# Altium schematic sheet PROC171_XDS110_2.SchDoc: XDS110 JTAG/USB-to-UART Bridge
size 431 x 279 mm; Date: Not shown in title block; ApprovedBy: Not shown in title block; CheckedBy: Not shown in title block; Author: Not shown in title block; CompanyName: Not shown in title block; Engineer: Not shown in title block; Organization: Not shown in title block; Address1: Not shown in title block; Address2: Not shown in title block; Address3: Not shown in title block; Address4: Not shown in title block; DocumentNumber: 26; Revision: Use project parameter SCH_Rev; SheetNumber: 26; SheetTotal: 27; PageSetup: Record=PageOptions¦CenterHorizontal=True¦CenterVertical=True¦PrintScale=1.00¦XCorrection=1.00¦YCorrection=1.00¦PrintKind=0¦BorderSize=5000000¦LeftOffset=0¦BottomOffset=0¦Orientation=2¦PaperLength=1000¦PaperWidth=1000¦Scale=100¦PaperSource=15¦PrintQuality=600¦MediaType=1¦DitherType=10¦PaperKind=Letter¦PrintScaleMode=1
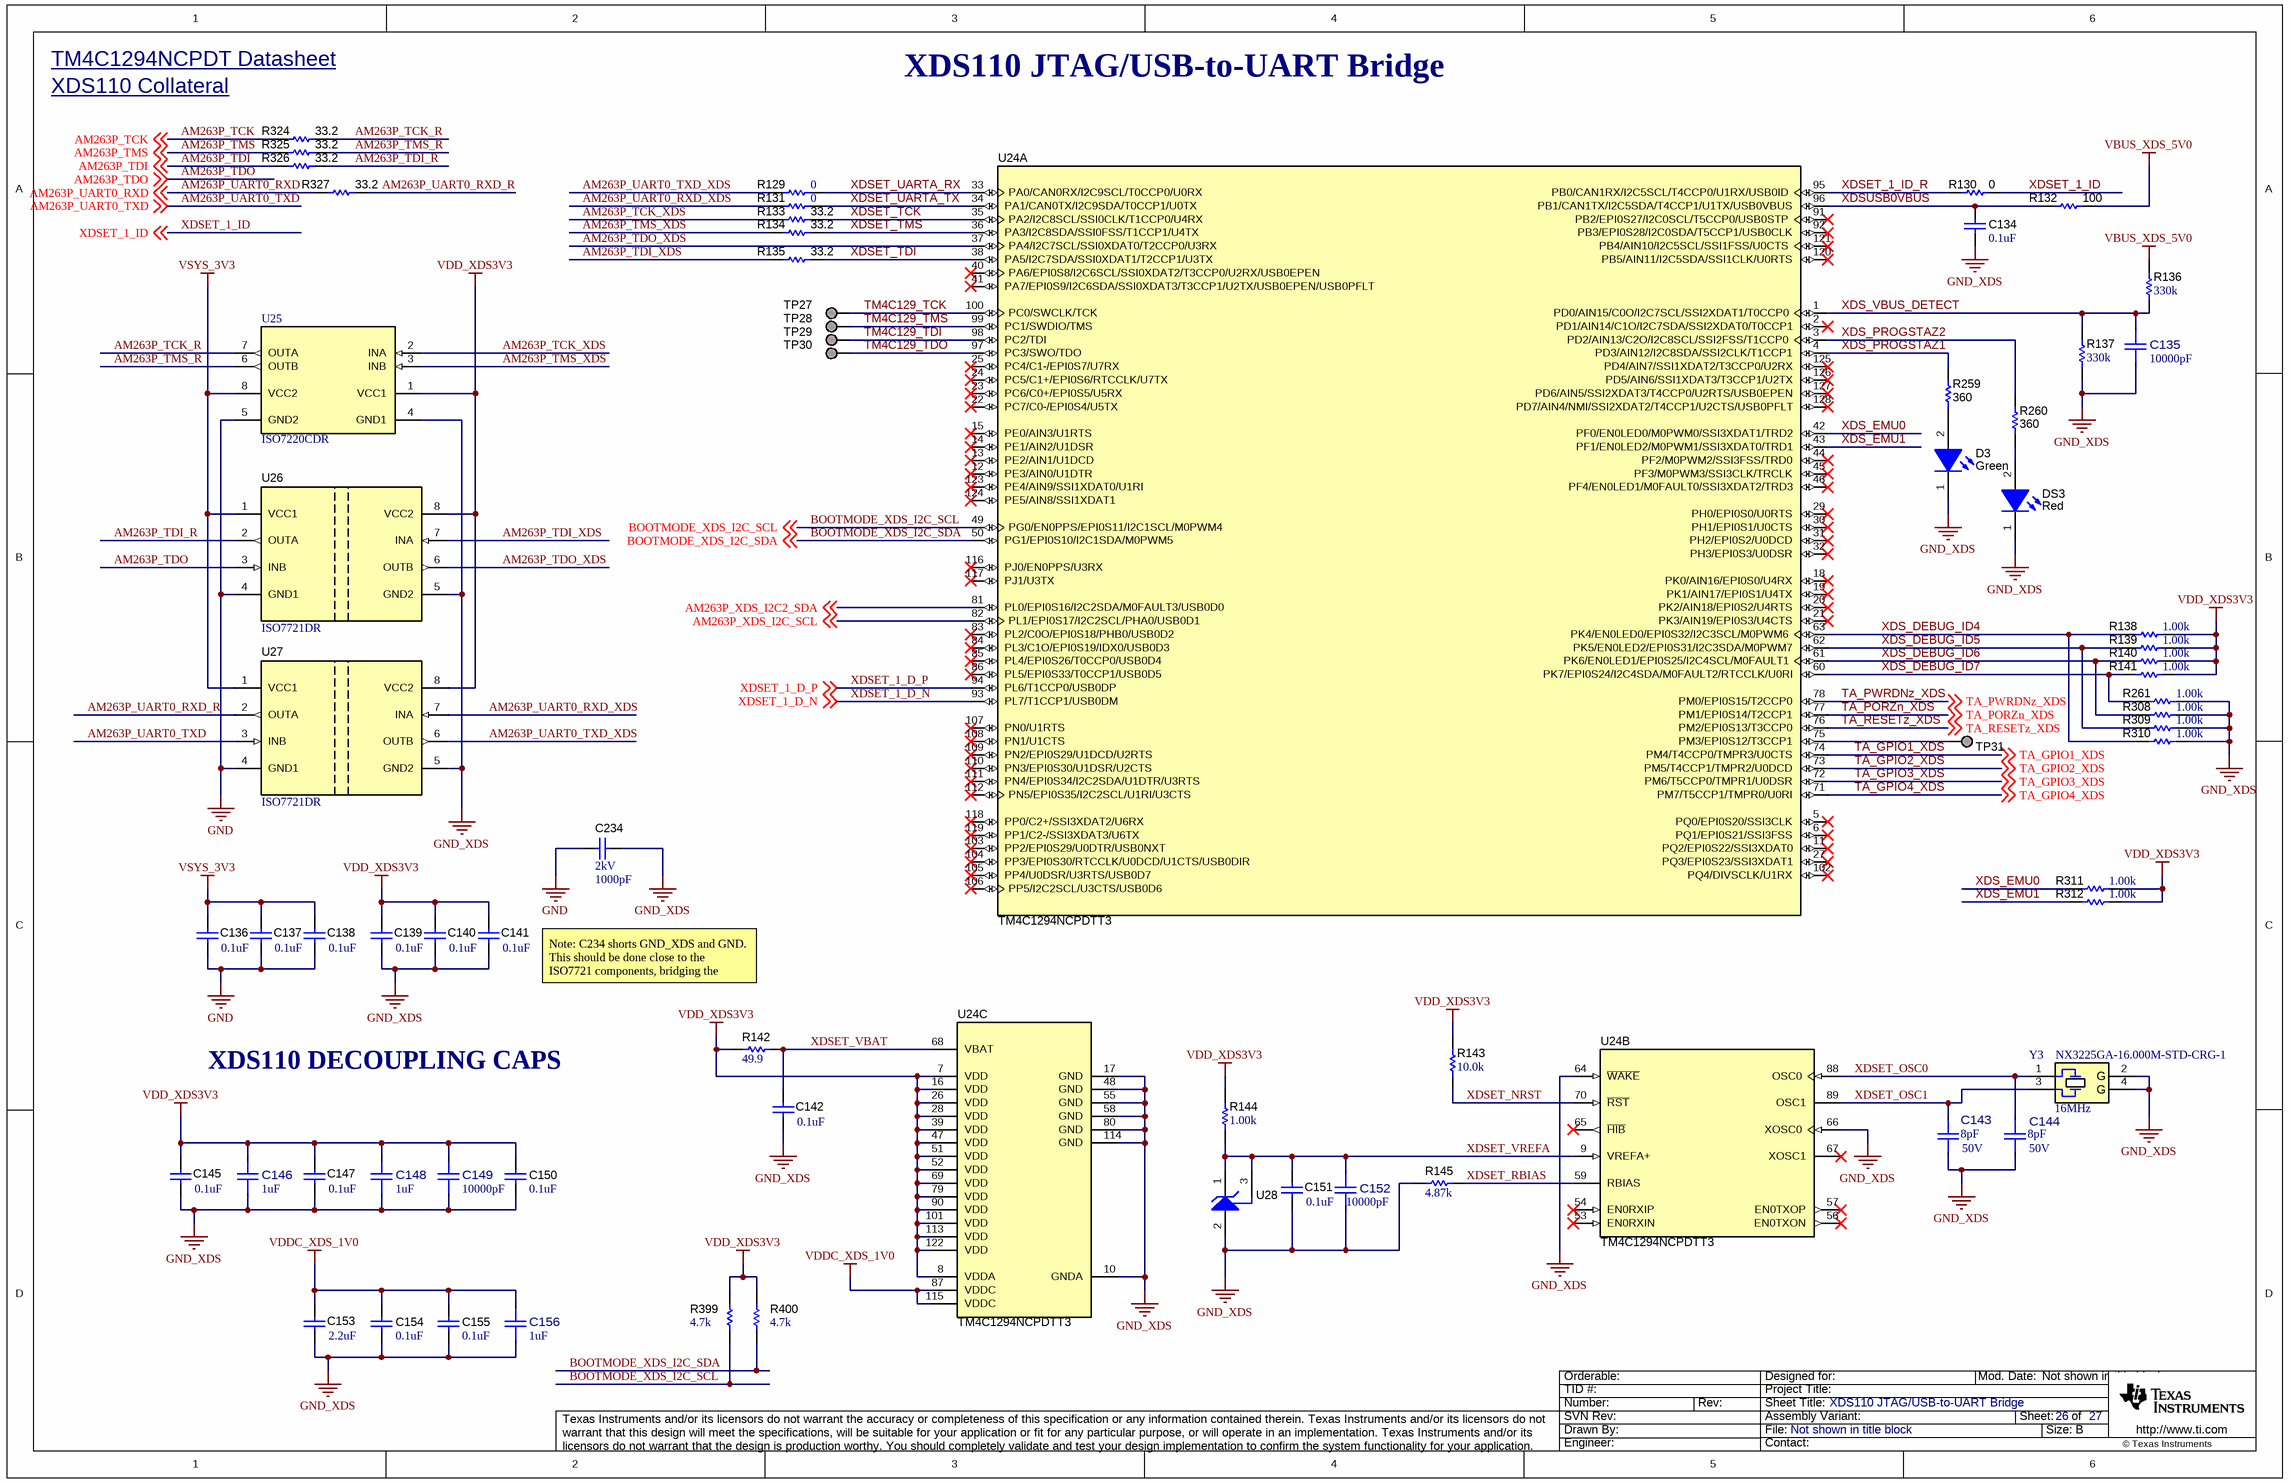
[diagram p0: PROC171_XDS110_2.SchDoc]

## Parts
C134  ValueDisplayed: 0.1uF  [0402]  (hidden comment: GRM155R71E104KE14D)
C135  ValueDisplayed: 10000pF  [FP-GRM1555C1E103JE01D_0402-MFG]  (hidden comment: GRM1555C1E103JE01D)
C136  ValueDisplayed: 0.1uF  [0402]  (hidden comment: GRM155R71E104KE14D)
C137  ValueDisplayed: 0.1uF  [0402]  (hidden comment: GRM155R71E104KE14D)
C138  ValueDisplayed: 0.1uF  [0402]  (hidden comment: GRM155R71E104KE14D)
C139  ValueDisplayed: 0.1uF  [0402]  (hidden comment: GRM155R71E104KE14D)
C140  ValueDisplayed: 0.1uF  [0402]  (hidden comment: GRM155R71E104KE14D)
C141  ValueDisplayed: 0.1uF  [0402]  (hidden comment: GRM155R71E104KE14D)
C142  ValueDisplayed: 0.1uF  [0402]  (hidden comment: GRM155R71E104KE14D)
C143  Cap_F: 8pF  VDC_V: 50V  [FP-GJM1555C1H8R0DB01D_0402-MFG]  (hidden comment: GJM1555C1H8R0DB01D)
C144  Cap_F: 8pF  VDC_V: 50V  [FP-GJM1555C1H8R0DB01D_0402-MFG]  (hidden comment: GJM1555C1H8R0DB01D)
C145  ValueDisplayed: 0.1uF  [0402]  (hidden comment: GRM155R71E104KE14D)
C146  ValueDisplayed: 1uF  [FP-GRM155C71A105KE11D_0402-MFG]  (hidden comment: GRM155C71A105KE11D)
C147  ValueDisplayed: 0.1uF  [0402]  (hidden comment: GRM155R71E104KE14D)
C148  ValueDisplayed: 1uF  [FP-GRM155C71A105KE11D_0402-MFG]  (hidden comment: GRM155C71A105KE11D)
C149  ValueDisplayed: 10000pF  [FP-GRM1555C1E103JE01D_0402-MFG]  (hidden comment: GRM1555C1E103JE01D)
C150  ValueDisplayed: 0.1uF  [0402]  (hidden comment: GRM155R71E104KE14D)
C151  ValueDisplayed: 0.1uF  [0402]  (hidden comment: GRM155R71E104KE14D)
C152  ValueDisplayed: 10000pF  [FP-GRM1555C1E103JE01D_0402-MFG]  (hidden comment: GRM1555C1E103JE01D)
C153  ValueDisplayed: 2.2uF  [0402]  (hidden comment: GRM155C81C225KE11D)
C154  ValueDisplayed: 0.1uF  [0402]  (hidden comment: GRM155R71E104KE14D)
C155  ValueDisplayed: 0.1uF  [0402]  (hidden comment: GRM155R71E104KE14D)
C156  ValueDisplayed: 1uF  [FP-GRM155C71A105KE11D_0402-MFG]  (hidden comment: GRM155C71A105KE11D)
C234  VDC_V: 2kV  ValueDisplayed: 1000pF  [1808]  (hidden comment: GR442QR73D102KW01L)
D3  value Green  [WL-SMCW_GREEN]  (hidden comment: 150060VS75000)
DS3  value Red  [WL-SMCW_RED]  (hidden comment: 150060RS75000)
R129  ValueDisplayed: 0  [0402]  (hidden comment: ERJ-2GE0R00X)
R130  ValueDisplayed: 0  [0402L]  (hidden comment: ERJ-2GE0R00X)
R131  ValueDisplayed: 0  [0402]  (hidden comment: ERJ-2GE0R00X)
R132  ValueDisplayed: 100  [0402L]  (hidden comment: ERJ-2GEJ101X)
R133  ValueDisplayed: 33.2  [0402]  (hidden comment: CRCW040233R2FKED)
R134  ValueDisplayed: 33.2  [0402]  (hidden comment: CRCW040233R2FKED)
R135  ValueDisplayed: 33.2  [0402]  (hidden comment: CRCW040233R2FKED)
R136  ValueDisplayed: 330k  [0402L]  (hidden comment: CRCW0402330KFKED)
R137  ValueDisplayed: 330k  [0402L]  (hidden comment: CRCW0402330KFKED)
R138  ValueDisplayed: 1.00k  [0402L]  (hidden comment: CRCW04021K00FKED)
R139  ValueDisplayed: 1.00k  [0402L]  (hidden comment: CRCW04021K00FKED)
R140  ValueDisplayed: 1.00k  [0402L]  (hidden comment: CRCW04021K00FKED)
R141  ValueDisplayed: 1.00k  [0402L]  (hidden comment: CRCW04021K00FKED)
R142  ValueDisplayed: 49.9  [0402L]  (hidden comment: CRCW040249R9FKED)
R143  ValueDisplayed: 10.0k  [0402L]  (hidden comment: CRCW040210K0FKED)
R144  ValueDisplayed: 1.00k  [0402L]  (hidden comment: CRCW04021K00FKED)
R145  ValueDisplayed: 4.87k  [0402L]  (hidden comment: CRCW04024K87FKED)
R259  ValueDisplayed: 360  [0402L]  (hidden comment: ERJ-2GEJ361X)
R260  ValueDisplayed: 360  [0402L]  (hidden comment: ERJ-2GEJ361X)
R261  ValueDisplayed: 1.00k  [0402L]  (hidden comment: CRCW04021K00FKED)
R308  ValueDisplayed: 1.00k  [0402L]  (hidden comment: CRCW04021K00FKED)
R309  ValueDisplayed: 1.00k  [0402L]  (hidden comment: CRCW04021K00FKED)
R310  ValueDisplayed: 1.00k  [0402L]  (hidden comment: CRCW04021K00FKED)
R311  ValueDisplayed: 1.00k  [0402L]  (hidden comment: CRCW04021K00FKED)
R312  ValueDisplayed: 1.00k  [0402L]  (hidden comment: CRCW04021K00FKED)
R324  ValueDisplayed: 33.2  [0402]  (hidden comment: CRCW040233R2FKED)
R325  ValueDisplayed: 33.2  [0402]  (hidden comment: CRCW040233R2FKED)
R326  ValueDisplayed: 33.2  [0402]  (hidden comment: CRCW040233R2FKED)
R327  ValueDisplayed: 33.2  [0402]  (hidden comment: CRCW040233R2FKED)
R399  ValueDisplayed: 4.7k  [0402]  (hidden comment: CRCW04024K70JNED)
R400  ValueDisplayed: 4.7k  [0402]  (hidden comment: CRCW04024K70JNED)
TP27  TESTPOINT  [TP_25MIL-SMT]  (value not drawn)  (no BOM)
TP28  TESTPOINT  [TP_25MIL-SMT]  (value not drawn)  (no BOM)
TP29  TESTPOINT  [TP_25MIL-SMT]  (value not drawn)  (no BOM)
TP30  TESTPOINT  [TP_25MIL-SMT]  (value not drawn)  (no BOM)
TP31  TESTPOINT  [TP_25MIL-SMT]  (value not drawn)  (no BOM)
U24  TM4C1294NCPDTT3  [PDT0128A]  (parts A,B,C of 3)
U25  ISO7220CDR  [D0008B_N]
U26  ISO7721DR  [D0008B_HV]
U27  ISO7721DR  [D0008B_HV]
U28  LM4040C25QDBZR  [DBZ0003A_N]  (value not drawn)
Y3  NX3225GA-16.000M-STD-CRG-1  Frequency_Fixed: 16MHz  [NDK_NX3225GA]

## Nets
GND: C136.1 C137.1 C138.1 C234.2 U25.5(GND2) U26.4(GND1) U27.4(GND1)
GND_XDS: C134.1 C135.2 C139.1 C140.1 C141.1 C142.2 C143.2 C144.2 C145.1 C146.1 C147.1 C148.1 C149.1 C150.1 C151.1 C152.2 C153.1 C154.1 C155.1 C156.1 C234.1 D3.1(K) DS3.1(K) R137.1 R145.1 R261.2 R308.2 R309.2 R310.2 U24.10(GNDA) U24.17(GND) U24.48(GND) U24.55(GND) U24.58(GND) U24.64(~{WAKE}) U24.66(XOSC0) U24.80(GND) U24.114(GND) U25.4(GND1) U26.5(GND2) U27.5(GND2) U28.2(ANODE) Y3.2(GND) Y3.4(GND)
VBUS_XDS_5V0: R132.2 R136.2
VDD_XDS3V3: C139.2 C140.2 C141.2 C145.2 C146.2 C147.2 C148.2 C149.2 C150.2 R138.2 R139.2 R140.2 R141.2 R142.2 R143.2 R144.2 R311.2 R312.2 R399.2 R400.2 U24.7(VDD) U24.8(VDDA) U24.16(VDD) U24.26(VDD) U24.28(VDD) U24.39(VDD) U24.47(VDD) U24.51(VDD) U24.52(VDD) U24.69(VDD) U24.79(VDD) U24.90(VDD) U24.101(VDD) U24.113(VDD) U24.122(VDD) U25.1(VCC1) U26.8(VCC2) U27.8(VCC2)
VDDC_XDS_1V0: C153.2 C154.2 C155.2 C156.2 U24.87(VDDC) U24.115(VDDC)
VSYS_3V3: C136.2 C137.2 C138.2 U25.8(VCC2) U26.1(VCC1) U27.1(VCC1)
AM263P_TCK: R324.1 ; off-sheet AM263P_TCK
AM263P_TCK_R: R324.2 U25.7(OUTA)
AM263P_TCK_XDS: R133.1 U25.2(INA)
AM263P_TDI: R326.1 ; off-sheet AM263P_TDI
AM263P_TDI_R: R326.2 U26.2(OUTA)
AM263P_TDI_XDS: R135.1 U26.7(INA)
AM263P_TDO: U26.3(INB) ; off-sheet AM263P_TDO
AM263P_TDO_XDS: U24.37(PA4/I2C7SCL/SSI0XDAT0/T2CCP0/U3RX) U26.6(OUTB)
AM263P_TMS: R325.1 ; off-sheet AM263P_TMS
AM263P_TMS_R: R325.2 U25.6(OUTB)
AM263P_TMS_XDS: R134.1 U25.3(INB)
AM263P_UART0_RXD: R327.1 ; off-sheet AM263P_UART0_RXD
AM263P_UART0_RXD_R: R327.2 U27.2(OUTA)
AM263P_UART0_RXD_XDS: R131.1 U27.7(INA)
AM263P_UART0_TXD: U27.3(INB) ; off-sheet AM263P_UART0_TXD
AM263P_UART0_TXD_XDS: R129.1 U27.6(OUTB)
AM263P_XDS_I2C2_SDA: U24.81(PL0/EPI0S16/I2C2SDA/M0FAULT3/USB0D0) ; off-sheet AM263P_XDS_I2C2_SDA
AM263P_XDS_I2C_SCL: U24.82(PL1/EPI0S17/I2C2SCL/PHA0/USB0D1) ; off-sheet AM263P_XDS_I2C_SCL
BOOTMODE_XDS_I2C_SCL: R399.1 U24.49(PG0/EN0PPS/EPI0S11/I2C1SCL/M0PWM4) ; off-sheet BOOTMODE_XDS_I2C_SCL
BOOTMODE_XDS_I2C_SDA: R400.1 U24.50(PG1/EPI0S10/I2C1SDA/M0PWM5) ; off-sheet BOOTMODE_XDS_I2C_SDA
TA_GPIO1_XDS: U24.74(PM4/T4CCP0/TMPR3/U0CTS) ; off-sheet TA_GPIO1_XDS
TA_GPIO2_XDS: U24.73(PM5/T4CCP1/TMPR2/U0DCD) ; off-sheet TA_GPIO2_XDS
TA_GPIO3_XDS: U24.72(PM6/T5CCP0/TMPR1/U0DSR) ; off-sheet TA_GPIO3_XDS
TA_GPIO4_XDS: U24.71(PM7/T5CCP1/TMPR0/U0RI) ; off-sheet TA_GPIO4_XDS
TA_PORZn_XDS: U24.77(PM1/EPI0S14/T2CCP1) ; off-sheet TA_PORZn_XDS
TA_PWRDNz_XDS: U24.78(PM0/EPI0S15/T2CCP0) ; off-sheet TA_PWRDNz_XDS
TA_RESETz_XDS: U24.76(PM2/EPI0S13/T3CCP0) ; off-sheet TA_RESETz_XDS
TM4C129_TCK: TP27.1 U24.100(PC0/SWCLK/TCK)
TM4C129_TDI: TP29.1 U24.98(PC2/TDI)
TM4C129_TDO: TP30.1 U24.97(PC3/SWO/TDO)
TM4C129_TMS: TP28.1 U24.99(PC1/SWDIO/TMS)
XDS_DEBUG_ID4: R138.1 R310.1 U24.63(PK4/EN0LED0/EPI0S32/I2C3SCL/M0PWM6)
XDS_DEBUG_ID5: R139.1 R309.1 U24.62(PK5/EN0LED2/EPI0S31/I2C3SDA/M0PWM7)
XDS_DEBUG_ID6: R140.1 R308.1 U24.61(PK6/EN0LED1/EPI0S25/I2C4SCL/M0FAULT1)
XDS_DEBUG_ID7: R141.1 R261.1 U24.60(PK7/EPI0S24/I2C4SDA/M0FAULT2/RTCCLK/U0RI)
XDS_EMU0: R311.1 U24.42(PF0/EN0LED0/M0PWM0/SSI3XDAT1/TRD2)
XDS_EMU1: R312.1 U24.43(PF1/EN0LED2/M0PWM1/SSI3XDAT0/TRD1)
XDS_PROGSTAZ1: R259.2 U24.4(PD3/AIN12/I2C8SDA/SSI2CLK/T1CCP1)
XDS_PROGSTAZ2: R260.2 U24.3(PD2/AIN13/C2O/I2C8SCL/SSI2FSS/T1CCP0)
XDS_VBUS_DETECT: C135.1 R136.1 R137.2 U24.1(PD0/AIN15/C0O/I2C7SCL/SSI2XDAT1/T0CCP0)
XDSET_1_D_N: U24.93(PL7/T1CCP1/USB0DM) ; off-sheet XDSET_1_D_N
XDSET_1_D_P: U24.94(PL6/T1CCP0/USB0DP) ; off-sheet XDSET_1_D_P
XDSET_1_ID: R130.1 ; off-sheet XDSET_1_ID
XDSET_1_ID_R: R130.2 U24.95(PB0/CAN1RX/I2C5SCL/T4CCP0/U1RX/USB0ID)
XDSET_NRST: R143.1 U24.70(~{RST})
XDSET_OSC0: C144.1 U24.88(OSC0) Y3.1
XDSET_OSC1: C143.1 U24.89(OSC1) Y3.3
XDSET_RBIAS: R145.2 U24.59(RBIAS)
XDSET_TCK: R133.2 U24.35(PA2/I2C8SCL/SSI0CLK/T1CCP0/U4RX)
XDSET_TDI: R135.2 U24.38(PA5/I2C7SDA/SSI0XDAT1/T2CCP1/U3TX)
XDSET_TMS: R134.2 U24.36(PA3/I2C8SDA/SSI0FSS/T1CCP1/U4TX)
XDSET_UARTA_RX: R129.2 U24.33(PA0/CAN0RX/I2C9SCL/T0CCP0/U0RX)
XDSET_UARTA_TX: R131.2 U24.34(PA1/CAN0TX/I2C9SDA/T0CCP1/U0TX)
XDSET_VBAT: C142.1 R142.1 U24.68(VBAT)
XDSET_VREFA: C151.2 C152.1 R144.1 U24.9(VREFA+) U28.1(CATHODE) U28.3(NC)
XDSUSB0VBUS: C134.2 R132.1 U24.96(PB1/CAN1TX/I2C5SDA/T4CCP1/U1TX/USB0VBUS)
NetD3_2: D3.2(A) R259.1
NetDS3_2: DS3.2(A) R260.1
NetTP31_1: TP31.1 U24.75(PM3/EPI0S12/T3CCP1)

Not connected (* = marked no-connect by the designer): U24 2(PD1/AIN14/C1O/I2C7SDA/SSI2XDAT0/T0CCP1)* 5(PQ0/EPI0S20/SSI3CLK)* 6(PQ1/EPI0S21/SSI3FSS)* 11(PQ2/EPI0S22/SSI3XDAT0)* 12(PE3/AIN0/U1DTR)* 13(PE2/AIN1/U1DCD)* 14(PE1/AIN2/U1DSR)* 15(PE0/AIN3/U1RTS)* 18(PK0/AIN16/EPI0S0/U4RX)* 19(PK1/AIN17/EPI0S1/U4TX)* 20(PK2/AIN18/EPI0S2/U4RTS)* 21(PK3/AIN19/EPI0S3/U4CTS)* 22(PC7/C0-/EPI0S4/U5TX)* 23(PC6/C0+/EPI0S5/U5RX)* 24(PC5/C1+/EPI0S6/RTCCLK/U7TX)* 25(PC4/C1-/EPI0S7/U7RX)* 27(PQ3/EPI0S23/SSI3XDAT1)* 29(PH0/EPI0S0/U0RTS)* 30(PH1/EPI0S1/U0CTS)* 31(PH2/EPI0S2/U0DCD)* 32(PH3/EPI0S3/U0DSR)* 40(PA6/EPI0S8/I2C6SCL/SSI0XDAT2/T3CCP0/U2RX/USB0EPEN)* 41(PA7/EPI0S9/I2C6SDA/SSI0XDAT3/T3CCP1/U2TX/USB0EPEN/USB0PFLT)* 44(PF2/M0PWM2/SSI3FSS/TRD0)* 45(PF3/M0PWM3/SSI3CLK/TRCLK)* 46(PF4/EN0LED1/M0FAULT0/SSI3XDAT2/TRD3)* 53(EN0RXIN)* 54(EN0RXIP)* 56(EN0TXON)* 57(EN0TXOP)* 65(~{HIB})* 67(XOSC1)* 83(PL2/C0O/EPI0S18/PHB0/USB0D2)* 84(PL3/C1O/EPI0S19/IDX0/USB0D3)* 85(PL4/EPI0S26/T0CCP0/USB0D4)* 86(PL5/EPI0S33/T0CCP1/USB0D5)* 91(PB2/EPI0S27/I2C0SCL/T5CCP0/USB0STP)* 92(PB3/EPI0S28/I2C0SDA/T5CCP1/USB0CLK)* 102(PQ4/DIVSCLK/U1RX)* 103(PP2/EPI0S29/U0DTR/USB0NXT)* 104(PP3/EPI0S30/RTCCLK/U0DCD/U1CTS/USB0DIR)* 105(PP4/U0DSR/U3RTS/USB0D7)* 106(PP5/I2C2SCL/U3CTS/USB0D6)* 107(PN0/U1RTS)* 108(PN1/U1CTS)* 109(PN2/EPI0S29/U1DCD/U2RTS)* 110(PN3/EPI0S30/U1DSR/U2CTS)* 111(PN4/EPI0S34/I2C2SDA/U1DTR/U3RTS)* 112(PN5/EPI0S35/I2C2SCL/U1RI/U3CTS)* 116(PJ0/EN0PPS/U3RX)* 117(PJ1/U3TX)* 118(PP0/C2+/SSI3XDAT2/U6RX)* 119(PP1/C2-/SSI3XDAT3/U6TX)* 120(PB5/AIN11/I2C5SDA/SSI1CLK/U0RTS)* 121(PB4/AIN10/I2C5SCL/SSI1FSS/U0CTS)* 123(PE4/AIN9/SSI1XDAT0/U1RI)* 124(PE5/AIN8/SSI1XDAT1)* 125(PD4/AIN7/SSI1XDAT2/T3CCP0/U2RX)* 126(PD5/AIN6/SSI1XDAT3/T3CCP1/U2TX)* 127(PD6/AIN5/SSI2XDAT3/T4CCP0/U2RTS/USB0EPEN)* 128(PD7/AIN4/NMI/SSI2XDAT2/T4CCP1/U2CTS/USB0PFLT)*

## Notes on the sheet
- XDS110 Collateral <https://software-dl.ti.com/ccs/esd/documents/xdsdebugprobes/emu_xds110.html>
- TM4C1294NCPDT Datasheet <http://www.ti.com/lit/ds/symlink/tm4c1294ncpdt.pdf>
- XDS110 JTAG/USB-to-UART Bridge
- Note: C234 shorts GND_XDS and GND. This should be done close to the ISO7721 components, bridging the air-gap between the two portions of the PCB
- XDS110 DECOUPLING CAPS

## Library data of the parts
C134 C136-C142 C145 C147 C150 C151 C154 C155 = CMP-0006659-2: CAP, CERM, 0.1 uF, 25 V, +/- 10%, X7R, 0402; Manufacturer: MuRata; TaMin_C: -55°C; Polarized: N; SizeAreaWB_mm2: 3; U/M: EA; Value: 0.1uF; TaMax_C: 125°C; SizeZ_mm: 0.6; SizeX_mm: 1; SizeY_mm: 0.5; Value2: 25V; Cap_F: 100nF; AEC Category: Q200; Value1: Unknown
C135 C149 C152 = CMP-0035343-1: Chip Multilayer Ceramic Capacitors for General Purpose, 0402, 10000pF, C0G, 30ppm/°C, 5%, 25V; Manufacturer: Murata; Value: 10nF; SizeZ_mm: 0.65mm; AEC Qualified: No
C143 C144 = CMP-0035284-1: Multi-Layer Ceramic Capacitor 8pF C0G  ±0.5pF 0402 Paper T/R; Manufacturer: Murata; TempCo: 30ppm/°C; AEC Qualified: No; SizeZ_mm: 0.55mm
C146 C148 C156 = CMP-0035346-1: 1µF ±10% 10V Ceramic Capacitor X7S 0402 (1005 Metric); Manufacturer: Murata; TempCo: 22%; SizeZ_mm: 0.6mm; AEC Qualified: No
C153 = CMP-0006526-2: CAP, CERM, 2.2 uF, 16 V, +/- 10%, X6S, 0402; Manufacturer: MuRata; TaMin_C: -55°C; Polarized: N; SizeAreaWB_mm2: 3; Value1: Unknown; U/M: EA; Value: 2.2uF; TaMax_C: 105°C; SizeZ_mm: 0.6; SizeX_mm: 1; SizeY_mm: 0.5; Value2: 16V; Cap_F: 2.2µF; AEC Category: Q200
C234 = CMP-0009436-2: CAP, CERM, 1000 pF, 2000 V, +/- 10%, X7R, 1808; Manufacturer: MuRata; TaMin_C: -55°C; Polarized: N; SizeAreaWB_mm2: 16.5; Value1: Unknown; U/M: EA; Value: 1000pF; TaMax_C: 125°C; SizeZ_mm: 2.03; SizeX_mm: 4.5; SizeY_mm: 2; Value2: 2000V; SizeArea_mm2: 9; Cap_F: 1nF; AEC Category: Q200
D3 = CMP-0002894-2: LED, Green, SMD; Manufacturer: Wurth Elektronik; Io_A: 20mA; Value1: W; Vf_V: 2V; Type: AlInGaP
DS3 = CMP-0002947-3: LED, Red, SMD; Manufacturer: Wurth Elektronik; Value1: 0.072W; Vf_V: 2V; Angle: 140; Tjmax_C: 85°C; Type: AlInGaP; Vr_V: 5V; Io_A: 30mA; Power_TotalModule: 72mW
R129 R131 = CMP-0026992-3: RES, 0, 5%, 0.1 W, AEC-Q200 Grade 0, 0402; Manufacturer: Panasonic; Power_W: 100mW; TempCo: 600 ppm/C; Value_Code: 0000; Value: 0; EIA_Code: E24; SizeX_mm: 1; SizeY_mm: 0.5; SizeZ_mm: 0.6; Value2: 0.1W; CompType: Resistor; AEC Qualified: Y; VDC_V: 50V; AEC Category: Q200; SizeAreaWB_mm2: 3; INSTALLATION: DNP
R130 = CMP-0026992-3: RES, 0, 5%, 0.1 W, AEC-Q200 Grade 0, 0402; Manufacturer: Panasonic; Power_W: 100mW; TempCo: 600 ppm/C; Value_Code: 0000; Value: 0; EIA_Code: E24; SizeX_mm: 1; SizeY_mm: 0.5; SizeZ_mm: 0.6; Value2: 0.1W; AEC Qualified: Y; VDC_V: 50V; AEC Category: Q200; SizeAreaWB_mm2: 3
R132 = CMP-0026993-2: RES, 100, 5%, 0.1 W, AEC-Q200 Grade 0, 0402; Manufacturer: Panasonic; Power_W: 100mW; TempCo: 200 ppm/C; Value_Code: 100R; U/M: EA; Value: 100; EIA_Code: E24; SizeX_mm: 1; SizeY_mm: 0.5; SizeZ_mm: 0.6; Value2: 0.1W; AEC Qualified: Y; AEC Grade: 0; AEC Category: Q200
R133-R135 R324-R327 = CMP-0026299-2: RES, 33.2, 1%, 0.063 W, AEC-Q200 Grade 0, 0402; Manufacturer: Vishay-Dale; Power_W: 63mW; TempCo: 100 ppm/C; Value_Code: 33R2; Value: 33.2; EIA_Code: E96; SizeX_mm: 1; SizeY_mm: 0.5; SizeZ_mm: 0.6; Value2: 0.063W; AEC Qualified: Y; VDC_V: 50V; AEC Category: Q200; AEC Grade: 0
R136 R137 = CMP-0078210-2: RES, 330 k, 1%, 0.063 W, AEC-Q200 Grade 0, 0402; Manufacturer: Vishay-Dale; SizeArea_mm2: 0.5; AEC Qualified: Y; AEC Category: Q200; Value: 330k; SizeZ_mm: 0.6; TempCo: 100 ppm/C; AEC Grade: 0; Power_W: 63mW; VDC_V: 50V; Value2: 0.063W; SizeX_mm: 1
R138-R141 R144 R261 R308-R312 = CMP-0026071-3: RES, 1.00 k, 1%, 0.063 W, AEC-Q200 Grade 0, 0402; Manufacturer: Vishay-Dale; Power_W: 63mW; TempCo: 100 ppm/C; Value_Code: 1k00; Value: 1.00k; EIA_Code: E96; Res_ohm: 1k; SizeX_mm: 1; SizeY_mm: 0.5; SizeZ_mm: 0.6; Value2: 0.063W; AEC Qualified: Y; VDC_V: 50V; AEC Category: Q200; AEC Grade: 0
R142 = CMP-0026404-2: RES, 49.9, 1%, 0.063 W, AEC-Q200 Grade 0, 0402; Manufacturer: Vishay-Dale; Power_W: 63mW; TempCo: 100 ppm/C; Value_Code: 49R9; Value: 49.9; EIA_Code: E96; SizeX_mm: 1; SizeY_mm: 0.5; SizeZ_mm: 0.6; Value2: 0.063W; AEC Qualified: Y; VDC_V: 50V; AEC Category: Q200; AEC Grade: 0
R143 = CMP-0025958-3: RES, 10.0 k, 1%, 0.063 W, AEC-Q200 Grade 0, 0402; Manufacturer: Vishay-Dale; Power_W: 63mW; TempCo: 100 ppm/C; Value_Code: 10k0; Value: 10.0k; EIA_Code: E96; Res_ohm: 10k; SizeX_mm: 1; SizeY_mm: 0.5; SizeZ_mm: 0.6; Value2: 0.063W; AEC Qualified: Y; VDC_V: 50V; AEC Category: Q200; AEC Grade: 0
R145 = CMP-0026413-2: RES, 4.87 k, 1%, 0.063 W, AEC-Q200 Grade 0, 0402; Manufacturer: Vishay-Dale; Power_W: 63mW; TempCo: 100 ppm/C; Value_Code: 4k87; Value: 4.87k; EIA_Code: E96; SizeX_mm: 1; SizeY_mm: 0.5; SizeZ_mm: 0.6; Value2: 0.063W; AEC Qualified: Y; VDC_V: 50V; AEC Category: Q200; AEC Grade: 0
R259 R260 = CMP-0078194-1: RES, 360, 5%, 0.1 W, AEC-Q200 Grade 0, 0402; Manufacturer: Panasonic; Value_Code: 360R; SizeArea_mm2: 0.5; AEC Qualified: Y; AEC Category: Q200; Value: 360; SizeZ_mm: 0.6; EIA_Code: E24; TempCo: 200 ppm/C; AEC Grade: 0; Power_W: 100mW; VDC_V: 50V; Value2: 0.1W; U/M: EA; SizeX_mm: 1
R399 R400 = CMP-0026938-5: RES, 4.7 k, 5%, 0.063 W, AEC-Q200 Grade 0, 0402; Manufacturer: Vishay-Dale; Power_W: 63mW; TempCo: 200 ppm/C; Value_Code: 4k70; Value: 4.7k; EIA_Code: E24; SizeX_mm: 1; SizeY_mm: 0.5; SizeZ_mm: 0.6; Value2: 0.063W; AEC Qualified: Y; VDC_V: 50V; AEC Category: Q200; AEC Grade: 0
TP27-TP31 = CMP-0078143-3: TEST POINT.  No entry in BOM.
U24 = CMP-0029856-2: Tiva C Series Microcontroller, 1024 KB Flash, 256 KB SRAM, 12 Bit, 20 Channels, -40 to 105 degC, 128-Pin TQFP (PDT), Green (RoHS & no Sb/Br), Tray; Manufacturer: Texas Instruments; ADC Channels: 20; CPU: ARM Cortex-M4; Flash: 1024 KB; ADC Resolution: 12 Bits; Max Speed: 120 MHz; SRAM: 256 KB; SizeAreaWB_mm2: 324.0; SizeArea_mm2: 256.0; SizeX_mm: 16.0; SizeZ_mm: 1.2; CompType: IC
U25 = CMP-0029369-1: 25 Mbps Dual Channels, 2 / 0, Digital Isolator, 3.3 V / 5 V, -40 to +125 degC, 8-pin SOIC (D), Green (RoHS & no Sb/Br); Manufacturer: Texas Instruments; Supply Voltage(s)(V): 3.3, 5; Prop Delay(Max)(ns): 42; Insulation Rating(VRMS): 2500; Datarate(Mbps): 25; TTL/CMOS Input Threshold: TTL; Rating: Catalog; Input Noise Filter: Yes
U26 U27 = CMP-0076059-2: High Speed, Robust EMC Dual-Channel Digital Isolator, D0008B (SOIC-8); Manufacturer: Texas Instruments; SizeY_mm: 4.9; SizeArea_mm2: 29.4; Rating: Catalog; CompType: IC; AEC Category: Q200; AEC Qualified: N; SizeZ_mm: 1.75; SizeAreaWB_mm2: 55.2; SizeX_mm: 6.0
U28 = CMP-0033001-1: Precision Micropower Shunt Voltage Reference, 0.5% accuracy, 2.5 V, 15 ppm / degC, 15 mA, -40 to 125 degC, 3-pin SOT-23 (DBZ), Green (RoHS & no Sb/Br); Manufacturer: Texas Instruments; Initial Accuracy @ 25/deg C(%): 0.5; Temp Coeff(Typ)(ppm/ degree C): 15; Temp Coeff(Max)(ppm/ degree C): 100; Rating: Catalog; Min Iz for Regulation(uA): 75; VO(V): 2.5
Y3 = CMP-0004635-3: Crystal, 16 MHz, 8pF, SMD; Manufacturer: NDK; TaMax_C: 70°C; TaMin_C: -10°C; Frequency Stability: +/-30ppm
